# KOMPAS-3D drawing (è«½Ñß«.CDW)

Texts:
  Колесо 2-й      ступени
  Noncommercial version
  Normal
  Ra0.8
  js10
  Symbol type B
  Ra3.2
  1. Твёрдость зубьев HB=170...190
  2. Неуказанные литейные радиусы 6мм
  3. Неуказанные литьевые уклоны 7
  4. Неуказанные предельные отклонения
  размероввалов - t2, остальных  t2/2
  Symbol
  Модуль
  Число зубьев
  Угол наклона
  Направление линиии зуба
  Нормальный исходный контур
  Коэф. смещения
  Степень точности
  Делительный диаметр
  Обозначение чертежа
  сопряжённого колеса
  МАМИ ДМ-03А-02.1.12
  правое
  ГОСТ 13755-81
  Ra6.3
  Сталь 40Л
  ГОСТ 4543-71
  Колесо 2-й
  ступени
Dimensions and other numbers on the sheet: 70; 24; 6 отверстий; 74,4; 20; 9; 2; 2 фаски; 0,010; 80; 114; 198; 290; 325; 30; 0,050; 0,016; 2,5; 128; 0; 320,00; 1:2; 1; 3; 4; 5; 6; 7; 8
